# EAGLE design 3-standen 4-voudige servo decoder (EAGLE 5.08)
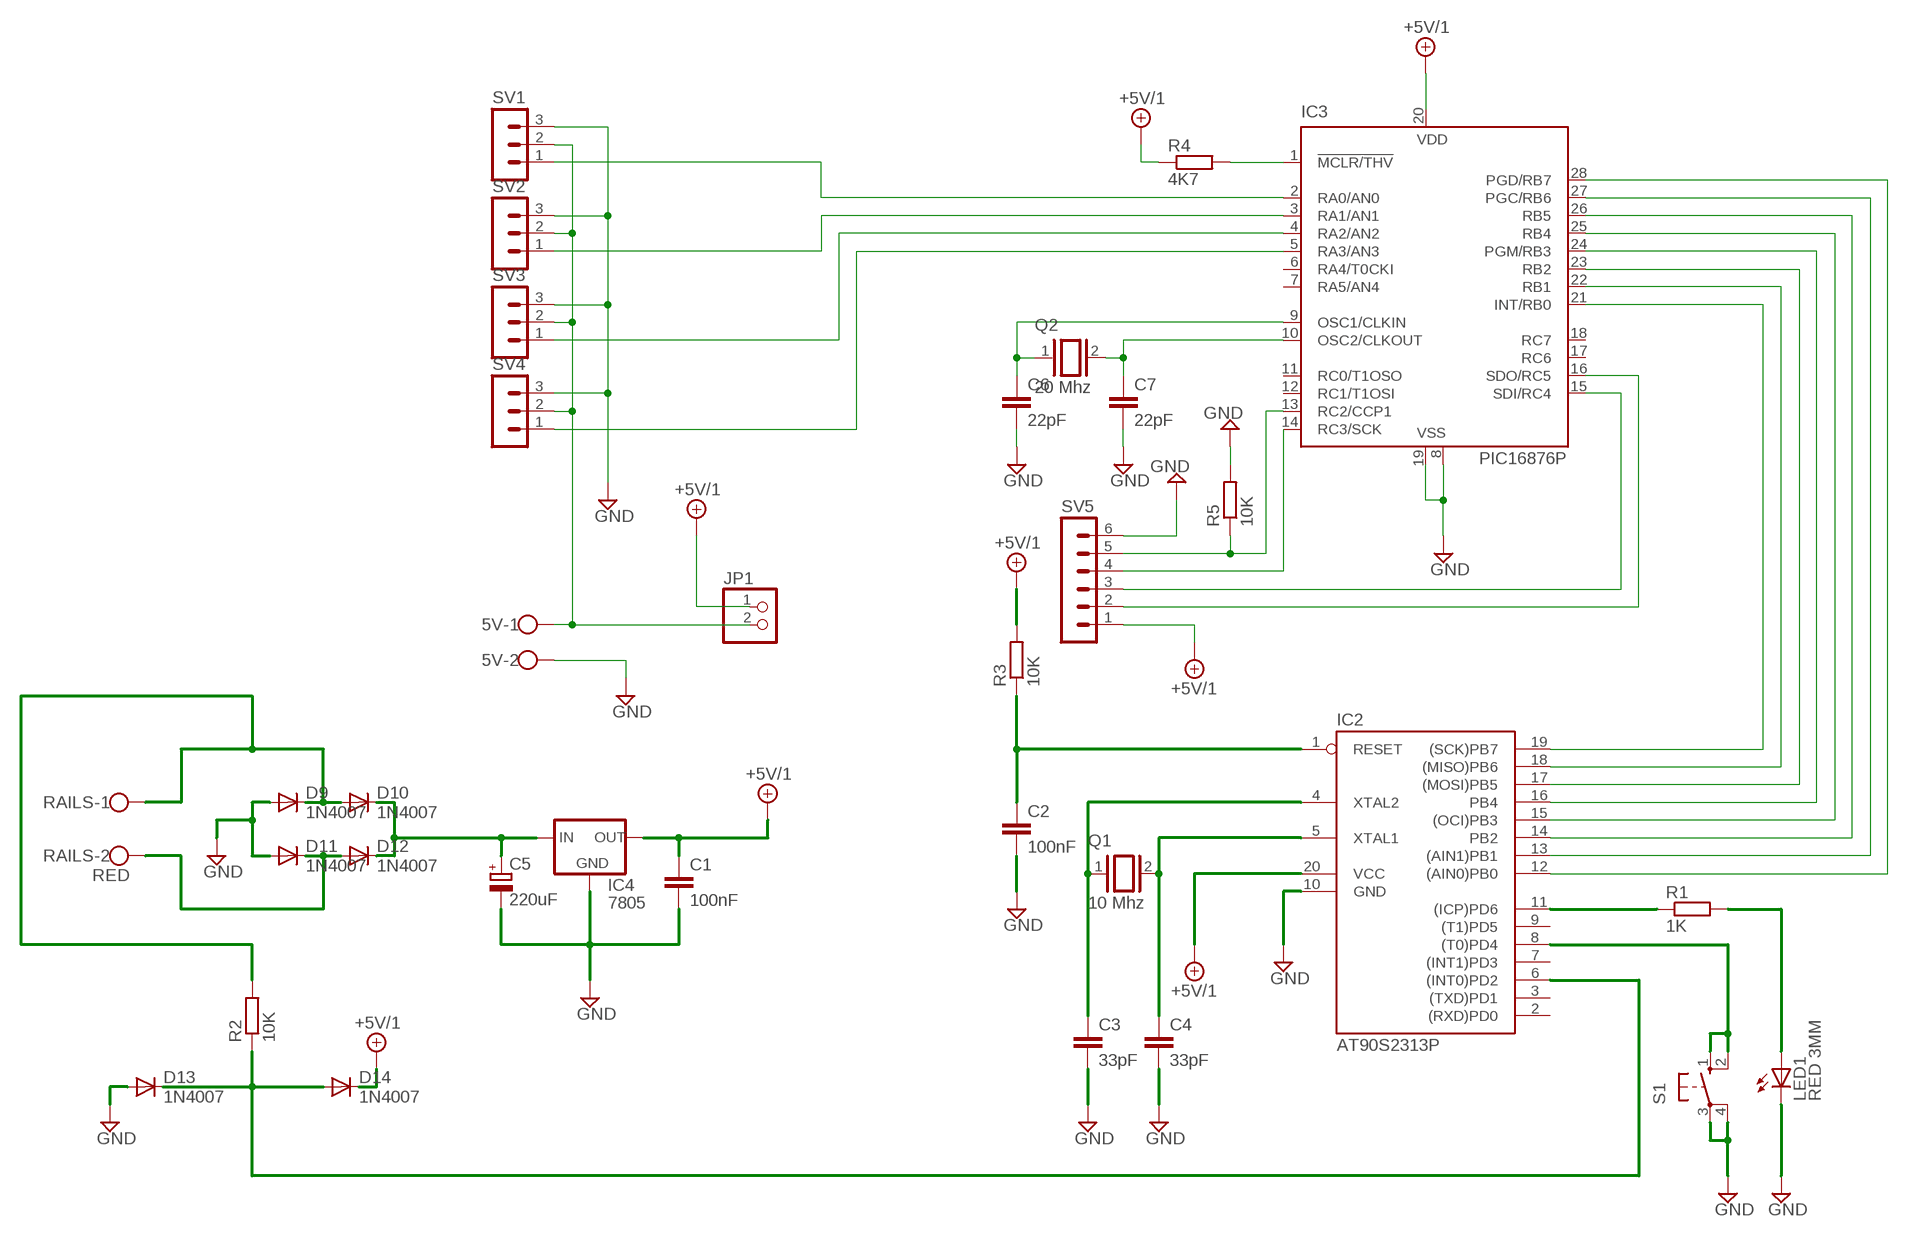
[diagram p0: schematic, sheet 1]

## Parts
5V  W237-102  [W237-102]
C1  100nF  C-EU025-025X050  [C025-025X050]
C2  100nF  C-EU025-025X050  [C025-025X050]
C3  33pF  C-EU025-025X050  [C025-025X050]
C4  33pF  C-EU025-025X050  [C025-025X050]
C5  220uF  CPOL-EUTT6D6  [TT5D6]
C6  22pF  C-EU025-025X050  [C025-025X050]
C7  22pF  C-EU025-025X050  [C025-025X050]
D9  1N4007  1N4148DO35-7  [DO35-7]
D10  1N4007  1N4148DO35-7  [DO35-7]
D11  1N4007  1N4148DO35-7  [DO35-7]
D12  1N4007  1N4148DO35-7  [DO35-7]
D13  1N4007  1N4148DO35-10  [DO35-10]
D14  1N4007  1N4148DO35-10  [DO35-10]
IC2  AT90S2313P  [DIL20]
IC3  PIC16876P  [DIL28-3]
IC4  7805  78MXXS  [78MXXS]
JP1  PINHD-1X2  [1X02]
LED1  RED 3MM  LED3MM  [LED3MM]
Q1  10 Mhz  XTAL/S  [QS]
Q2  20 Mhz  XTAL/S  [QS]
R1  1K  R-EU_0207/2V  [0207/2V]
R2  10K  R-EU_0204/5  [0204/5]
R3  10K  R-EU_0207/10  [0207/10]
R4  4K7  R-EU_0207/2V  [0207/2V]
R5  10K  R-EU_0207/2V  [0207/2V]
RAILS  RED  W237-102  [W237-102]
S1  10-XX  [B3F-10XX]
SV1  MA03-1  [MA03-1]
SV2  MA03-1  [MA03-1]
SV3  MA03-1  [MA03-1]
SV4  MA03-1  [MA03-1]
SV5  MA06-1  [MA06-1]

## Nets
+5V/1: C1.1 D14.C IC2.20(VCC) IC3.20(VDD) IC4.OUT JP1.1 R3.2 R4.1 SV5.1
GND: 5V.2 C1.2 C2.2 C3.2 C4.2 C5.- C6.2 C7.2 D9.A D11.A D13.A IC2.10(GND) IC3.8(VSS) IC3.19(VSS) IC4.GND LED1.K(C) R5.2 S1.3(P) S1.4(P1) SV1.3 SV2.3 SV3.3 SV4.3 SV5.6
N$1: IC2.19((SCK)PB7) IC3.21(INT/RB0)
N$2: IC2.18((MISO)PB6) IC3.22(RB1)
N$3: IC2.17((MOSI)PB5) IC3.23(RB2)
N$4: IC2.16(PB4) IC3.24(PGM/RB3)
N$5: IC2.15((OCI)PB3) IC3.25(RB4)
N$6: IC2.14(PB2) IC3.26(RB5)
N$7: IC2.13((AIN1)PB1) IC3.27(PGC/RB6)
N$8: IC2.12((AIN0)PB0) IC3.28(PGD/RB7)
N$9: C7.1 IC3.10(OSC2/CLKOUT) Q2.2
N$10: C6.1 IC3.9(OSC1/CLKIN) Q2.1
N$11: IC3.1(!MCLR/THV) R4.2
N$12: IC3.2(RA0/AN0) SV1.1
N$13: IC3.3(RA1/AN1) SV2.1
N$14: IC3.4(RA2/AN2) SV3.1
N$15: IC3.5(RA3/AN3) SV4.1
N$16: IC3.13(RC2/CCP1) R5.1 SV5.5
N$17: 5V.1 JP1.2 SV1.2 SV2.2 SV3.2 SV4.2
N$18: IC3.14(RC3/SCK) SV5.4
N$19: IC3.15(SDI/RC4) SV5.3
N$20: IC3.16(SDO/RC5) SV5.2
N$42: IC2.8((T0)PD4) S1.1(S) S1.2(S1)
N$43: C4.1 IC2.5(XTAL1) Q1.2
N$44: IC2.11((ICP)PD6) R1.1
N$45: LED1.A R1.2
N$46: D13.C D14.A IC2.6((INT0)PD2) R2.1
N$47: C5.+ D10.C D12.C IC4.IN
N$48: D9.C D10.A R2.2 RAILS.1
N$49: D11.C D12.A RAILS.2
N$50: C3.1 IC2.4(XTAL2) Q1.1
N$51: C2.1 IC2.1(RESET) R3.1
Unconnected: IC2.2((RXD)PD0) IC2.3((TXD)PD1) IC2.7((INT1)PD3) IC2.9((T1)PD5) IC3.6(RA4/T0CKI) IC3.7(RA5/AN4) IC3.11(RC0/T1OSO) IC3.12(RC1/T1OSI) IC3.17(RC6) IC3.18(RC7)

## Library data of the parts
5V RAILS = con-wago-500:W237-102: WAGO SCREW CLAMP
C1-C4 C6 C7 = rcl:C-EU: CAPACITOR, European symbol
C5 = rcl:CPOL-EU: POLARIZED CAPACITOR, European symbol
D9-D14 = diode:1N4148: DIODE
IC2 = atmel:AT90S2313: MICROCONTROLLER 2 Kbytes FLASH 128 bytes SRAM 128 bytes EEPROM UART
IC3 = microchip:PIC16*876: MICROCONTROLLER flash type
IC4 = v-reg:78MXXS: VOLTAGE REGULATOR
JP1 = pinhead:PINHD-1X2: PIN HEADER
LED1 = led:LED: LED
Q1 Q2 = special:XTAL/S: CRYSTAL
R1-R5 = resistor:R-EU_: RESISTOR, European symbol
S1 = switch-omron:10-XX: OMRON SWITCH
SV1-SV4 = con-lstb:MA03-1: PIN HEADER
SV5 = con-lstb:MA06-1: PIN HEADER

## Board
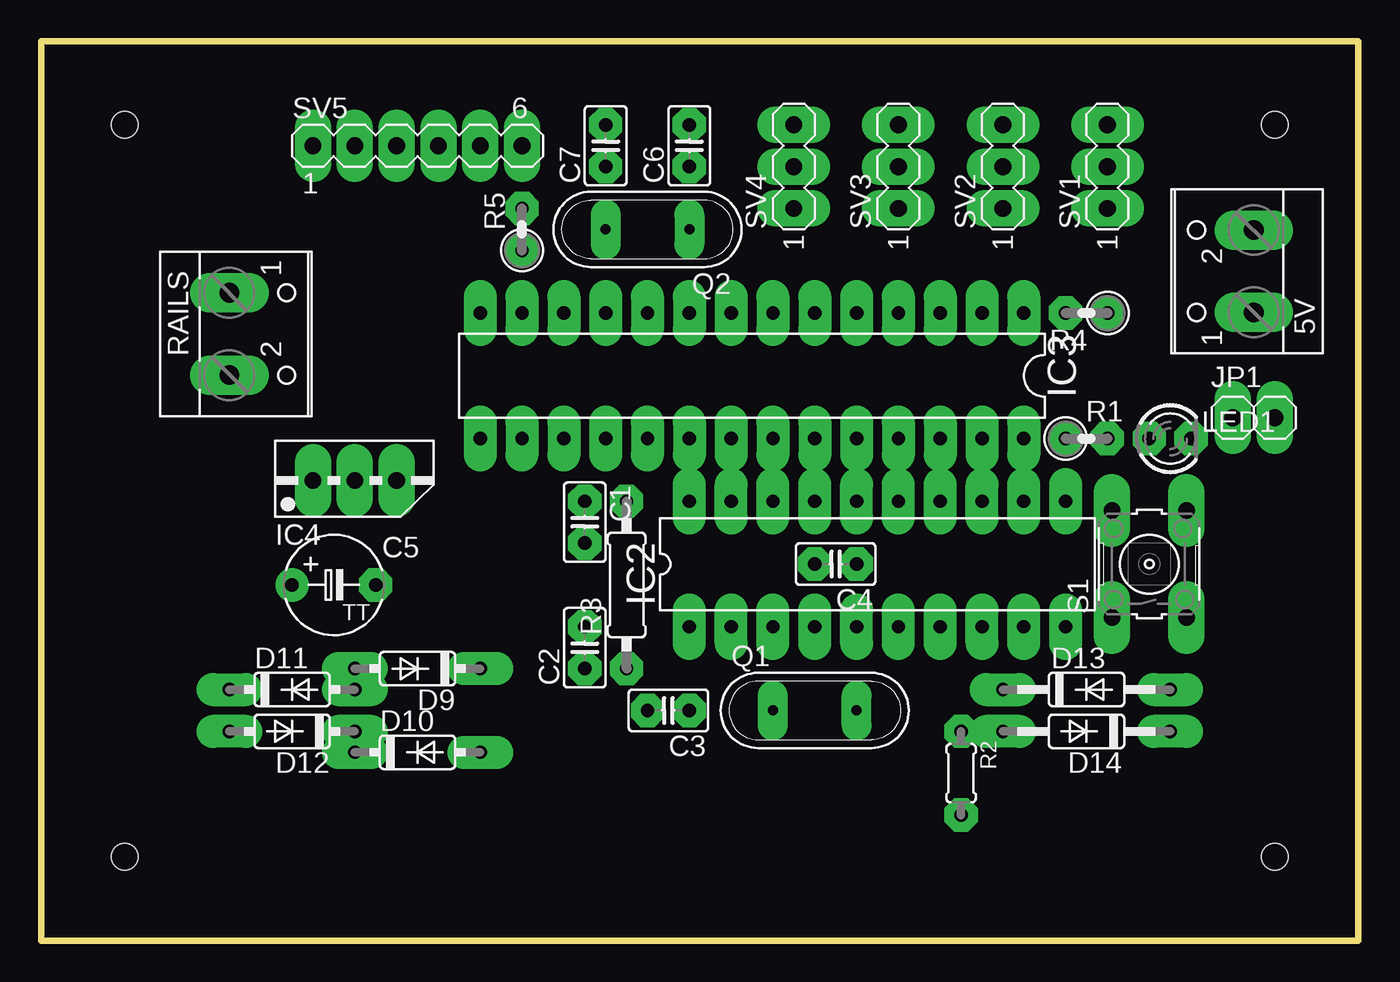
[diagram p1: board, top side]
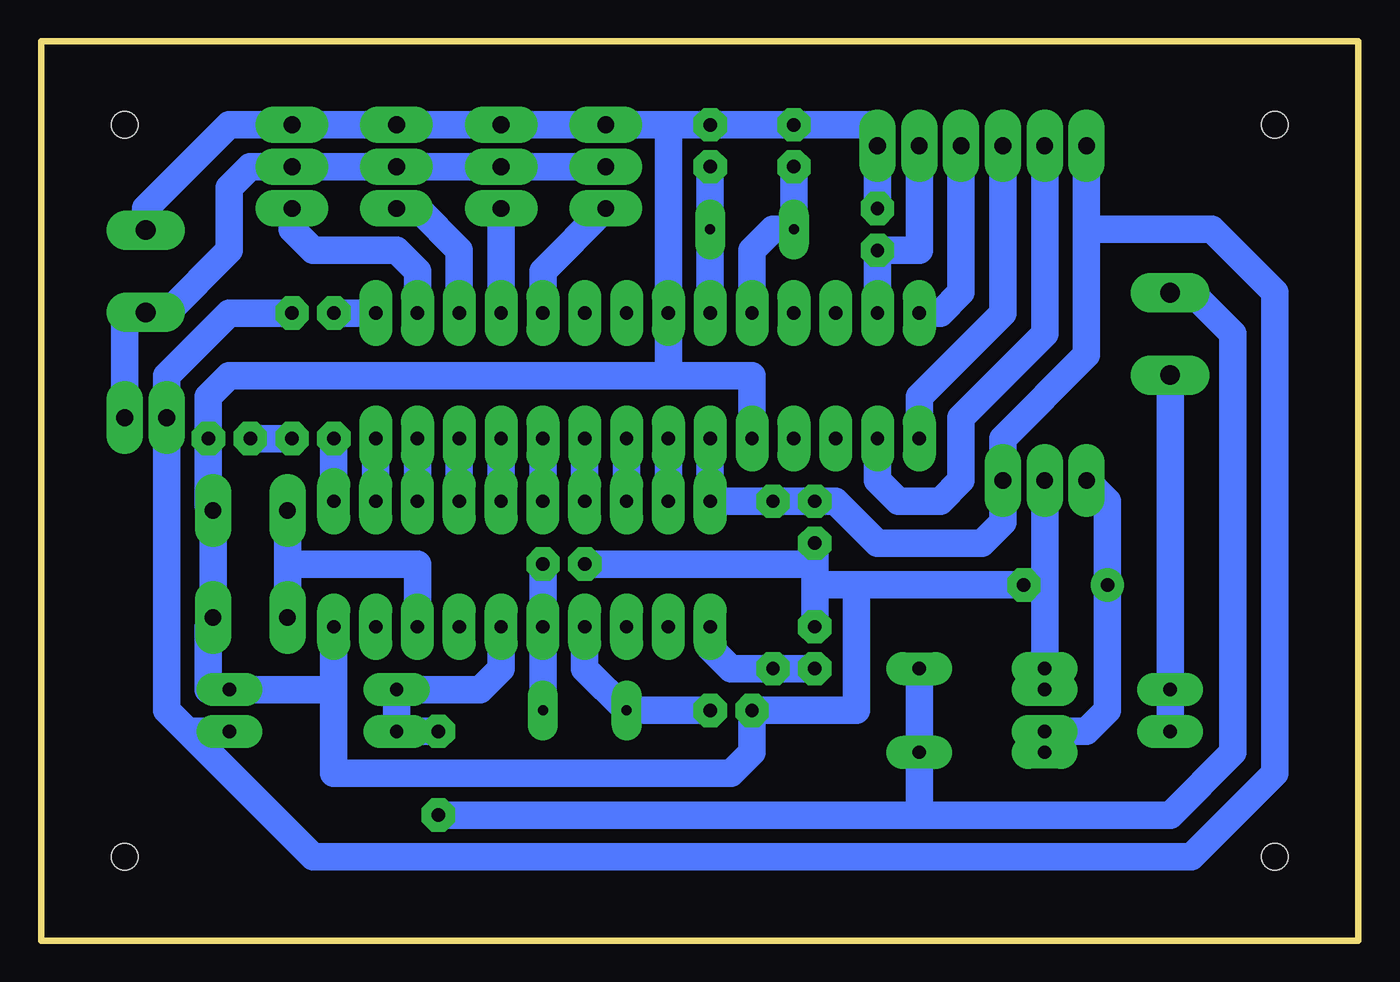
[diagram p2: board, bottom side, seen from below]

Size 80.01 x 54.61 mm. Coordinates in mm from the lower left corner, seen from the top.
Outline: 0,0 80.01,0 80.01,54.61 0,54.61 0,0
Copper layers (1*16): Top 1mm / dielectric 1.5mm / Bottom 1mm
Design rules "DRC settings middle": minimum track width 1.2mm, minimum drill 24mil, track to track 0.4mm, track to pad 0.4mm, pad to pad 0.4mm, via to via 0.4mm, smd to smd 8mil, copper to edge 0.5mm, drill to drill 0.5mm, minimum pad ring 0.6mm, minimum via ring 1mm, stop-mask expansion 4mil, vias tented up to drill 0mil, thermal gap 10mil
Holes 1.6 mm at 5.08,49.53 74.93,49.53 5.08,5.08 74.93,5.08

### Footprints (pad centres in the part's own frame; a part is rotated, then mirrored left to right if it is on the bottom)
W237-102 = drill 1.194 long: 1 -2.5,-1.27; 2 2.5,-1.27
C025-025X050 = drill 0.813 octagon: 1 -1.27,0; 2 1.27,0
TT5D6 = drill 0.813 round: + -2.54,0 | drill 0.813 octagon: - 2.54,0
DO35-7 = drill 0.813 long: A 3.81,0; C -3.81,0
DO35-10 = drill 0.813 long: A 5.08,0; C -5.08,0
DIL20 = drill 0.813 long: 1 -11.43,-3.81; 2 -8.89,-3.81; 3 -6.35,-3.81; 4 -3.81,-3.81; 5 -1.27,-3.81; 6 1.27,-3.81; 7 3.81,-3.81; 8 6.35,-3.81; 9 8.89,-3.81; 10 11.43,-3.81; 11 11.43,3.81; 12 8.89,3.81; 13 6.35,3.81; 14 3.81,3.81; 15 1.27,3.81; 16 -1.27,3.81; 17 -3.81,3.81; 18 -6.35,3.81; 19 -8.89,3.81; 20 -11.43,3.81
DIL28-3 = drill 0.813 long: 1 -16.51,-3.81; 2 -13.97,-3.81; 3 -11.43,-3.81; 4 -8.89,-3.81; 5 -6.35,-3.81; 6 -3.81,-3.81; 7 -1.27,-3.81; 8 1.27,-3.81; 9 3.81,-3.81; 10 6.35,-3.81; 11 8.89,-3.81; 12 11.43,-3.81; 13 13.97,-3.81; 14 16.51,-3.81; 15 16.51,3.81; 16 13.97,3.81; 17 11.43,3.81; 18 8.89,3.81; 19 6.35,3.81; 20 3.81,3.81; 21 1.27,3.81; 22 -1.27,3.81; 23 -3.81,3.81; 24 -6.35,3.81; 25 -8.89,3.81; 26 -11.43,3.81; 27 -13.97,3.81; 28 -16.51,3.81
78MXXS = drill 1.016 long: GND 0,-2.54; IN -2.54,-2.54; OUT 2.54,-2.54
1X02 = drill 1.016 long: 1 -1.27,0; 2 1.27,0
LED3MM = drill 0.813 octagon: A -1.27,0; K 1.27,0
QS = drill 0.61 long: 1 -2.54,0; 2 2.54,0
0207/2V = drill 0.813 octagon: 1 -1.27,0; 2 1.27,0
0204/5 = drill 0.813 octagon: 1 -2.54,0; 2 2.54,0
0207/10 = drill 0.813 octagon: 1 -5.08,0; 2 5.08,0
B3F-10XX = drill 1.016 long: 1 -3.251,2.261; 2 3.251,2.261; 3 -3.251,-2.261; 4 3.251,-2.261
MA03-1 = drill 1.016 long: 1 -2.54,0; 2 0,0; 3 2.54,0
MA06-1 = drill 1.016 long: 1 -6.35,0; 2 -3.81,0; 3 -1.27,0; 4 1.27,0; 5 3.81,0; 6 6.35,0

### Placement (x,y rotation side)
5V  72.39,40.64 90 top
C1  33.02,25.4 270 top
C2  33.02,17.78 90 top
C3  38.1,13.97 180 top
C4  48.26,22.86 180 top
C5  17.78,21.59 0 top
C6  39.37,48.26 90 top
C7  34.29,48.26 90 top
D9  22.86,16.51 180 top
D10  22.86,11.43 0 top
D11  15.24,15.24 0 top
D12  15.24,12.7 180 top
D13  63.5,15.24 0 top
D14  63.5,12.7 180 top
IC2  50.8,22.86 0 top
IC3  43.18,34.29 180 top
IC4  19.05,30.48 0 top
JP1  73.66,31.75 0 top
LED1  68.58,30.48 0 top
Q1  46.99,13.97 0 top
Q2  36.83,43.18 180 top
R1  63.5,30.48 0 top
R2  55.88,10.16 270 top
R3  35.56,21.59 90 top
R4  63.5,38.1 180 top
R5  29.21,43.18 90 top
RAILS  12.7,36.83 270 top
S1  67.31,22.86 90 top
SV1  64.77,46.99 90 top
SV2  58.42,46.99 90 top
SV3  52.07,46.99 90 top
SV4  45.72,46.99 90 top
SV5  22.86,48.26 0 top

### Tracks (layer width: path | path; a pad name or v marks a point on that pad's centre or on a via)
+5V/1
  Bottom 1.676: IC3.20 IC2.20 R3.2 C1.1 31.75,26.67 29.21,24.13 22.86,24.13 21.59,25.4 IC4.OUT 21.59,30.48 16.51,35.56 16.51,43.18 | R4.1 68.58,38.1 72.39,34.29 JP1.1 72.39,13.97 71.12,12.7 | 16.51,43.18 SV5.1 | 71.12,12.7 D14.C | 71.12,12.7 63.5,5.08 10.16,5.08 5.08,10.16 5.08,39.37 8.89,43.18 16.51,43.18
GND
  Bottom 1.676: 33.02,21.59 C2.2 | 33.02,21.59 33.02,22.86 | 33.02,22.86 C1.2 | C6.2 41.91,49.53 IC3.8 41.91,34.29 | C6.2 C7.2 29.21,49.53 SV5.6 R5.2 | C6.2 SV4.3 SV3.3 SV2.3 SV1.3 68.58,49.53 73.66,44.45 5V.2 73.66,43.18 | IC3.19 36.83,34.29 41.91,34.29 | 30.48,21.59 C5.- 19.05,21.59 | 30.48,21.59 33.02,21.59 | 30.48,21.59 30.48,13.97 C3.2 36.83,11.43 38.1,10.16 62.23,10.16 62.23,15.24 | 19.05,21.59 D9.A D11.A | 41.91,34.29 68.58,34.29 69.85,33.02 LED1.K 69.85,26.39 S1.4 S1.3 69.57,19.33 69.85,19.05 69.85,15.24 D13.A 62.23,15.24 | 33.02,22.86 C4.2 | 19.05,21.59 IC4.GND | 62.23,15.24 IC2.10
N$1
  Bottom 1.676: IC2.19 IC3.21
N$2
  Bottom 1.676: IC2.18 IC3.22
N$3
  Bottom 1.676: IC2.17 IC3.23
N$4
  Bottom 1.676: IC2.16 IC3.24
N$5
  Bottom 1.676: IC2.15 IC3.25
N$6
  Bottom 1.676: IC2.14 IC3.26
N$7
  Bottom 1.676: IC2.13 IC3.27
N$8
  Bottom 1.676: IC2.12 IC3.28
N$9
  Bottom 1.676: IC3.10 36.83,41.91 35.56,43.18 Q2.2 C7.1
N$10
  Bottom 1.676: IC3.9 Q2.1 C6.1
N$11
  Bottom 1.676: IC3.1 R4.2
N$12
  Bottom 1.676: IC3.2 57.15,40.64 58.42,41.91 63.5,41.91 64.77,43.18 SV1.1
N$13
  Bottom 1.676: SV2.1 57.15,44.45 54.61,41.91 IC3.3
N$14
  Bottom 1.676: IC3.4 SV3.1
N$15
  Bottom 1.676: IC3.5 49.53,40.64 SV4.1
N$16
  Bottom 1.676: IC3.13 R5.1 26.67,41.91 SV5.5
N$17
  Bottom 1.676: SV4.2 SV3.2 SV2.2 SV1.2 67.31,46.99 68.58,45.72 68.58,41.91 72.39,38.1 73.62,38.1 5V.1 73.7,38.1 74.93,38.1 JP1.2
N$18
  Bottom 1.676: IC3.14 25.4,38.1 24.13,39.37 SV5.4
N$19
  Bottom 1.676: IC3.15 26.67,33.02 21.59,38.1 SV5.3
N$20
  Bottom 1.676: IC3.16 29.21,27.94 27.94,26.67 25.4,26.67 24.13,27.94 24.13,31.75 19.05,36.83 SV5.2
N$42
  Bottom 1.676: 65.05,22.86 S1.1 | 65.05,22.86 S1.2 | IC2.8 57.15,22.86 65.05,22.86
N$43
  Bottom 1.676: Q1.2 IC2.5 C4.1
N$44
  Bottom 1.676: IC2.11 R1.1
N$45
  Bottom 1.676: R1.2 LED1.A
N$46
  Bottom 1.676: IC2.6 52.07,16.51 53.34,15.24 D13.C D14.A R2.1
N$47
  Bottom 1.676: D10.C D12.C 16.51,12.7 15.24,13.97 C5.+ 15.24,26.67 IC4.IN
N$48
  Bottom 1.676: D9.C D10.A 26.67,7.62 | RAILS.1 10.12,39.33 7.62,36.83 7.62,11.43 11.43,7.62 26.67,7.62 | 26.67,7.62 R2.2
N$49
  Bottom 1.676: D12.A D11.C RAILS.2
N$50
  Bottom 1.676: IC2.4 46.99,16.51 Q1.1 C3.1
N$51
  Bottom 1.676: IC2.1 39.37,17.78 38.1,16.51 R3.1 C2.1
